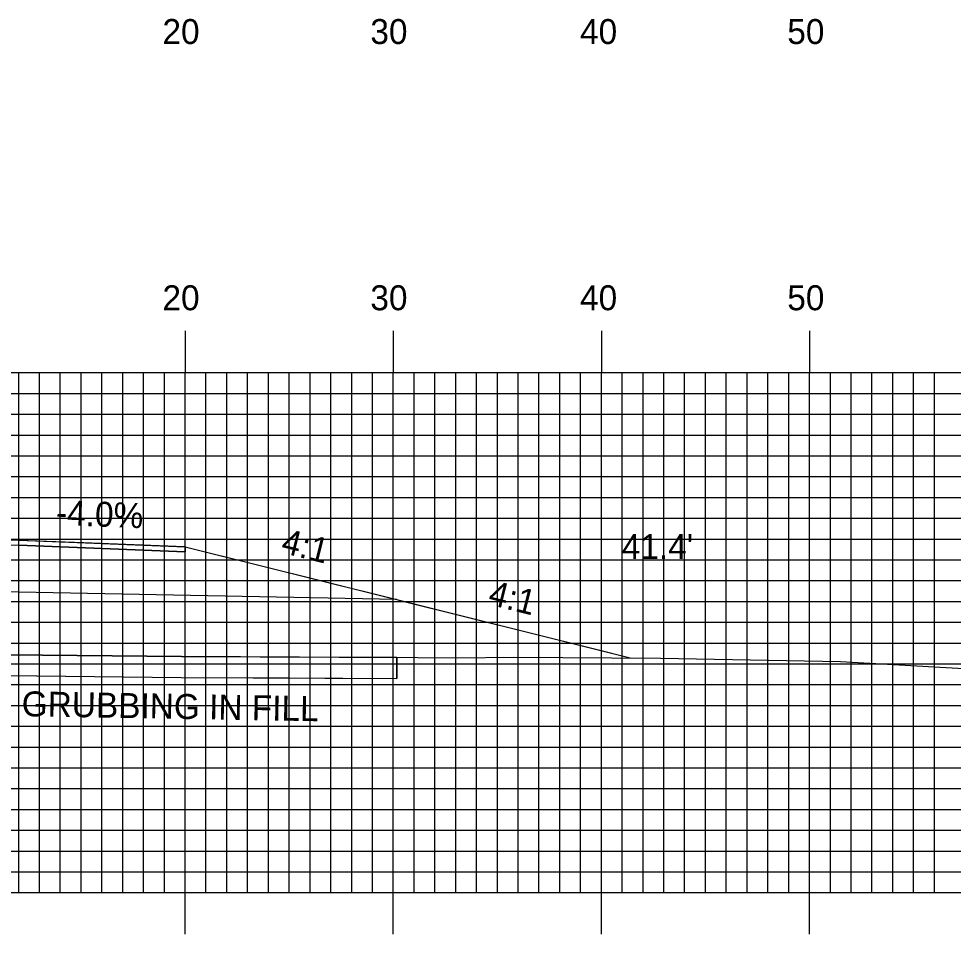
# Model space of a CAD drawing. Extents: x 1771629 to 1771972, y 442591 to 442811.
# Drawn here: x 1771806.58 to 1771851.49, y 442696.66 to 442740.68 of the extents above; entities that cross this region are included whole.
import ezdxf

# ---------------------------------------------------------------- set-up
doc = ezdxf.new("R2010")
doc.units = 0
for name, color, linetype in [('ANNOTATION', 7, 'Continuous'), ('D_Roadway_Centerline', 7, 'Continuous'), ('D_Roadway_Edge_Shoulder', 7, 'Continuous'), ('D_Roadway_SlopeLines', 7, 'Continuous'), ('D_Roadway_SubGrade', 7, 'Continuous'), ('D_Text_Standard', 7, 'Continuous'), ('GRUBBING IN FILL', 7, 'Continuous'), ('H_V ANNOTATION', 7, 'Continuous'), ('MAJOR', 7, 'Continuous'), ('MINOR', 7, 'Continuous'), ('S_Roadway_Centerline', 7, 'Continuous')]:
    doc.layers.add(name, color=color, linetype=linetype)

msp = doc.modelspace()

# ---------------------------------------------------------------- linework, layer by layer
at = {"layer": 'D_Roadway_Centerline'}
msp.add_lwpolyline([(1771760.497, 442711.776), (1771764.04, 442712.662), (1771764.407, 442712.753), (1771767.076, 442713.421), (1771774.552, 442715.29), (1771774.581, 442715.297), (1771776.908, 442715.39), (1771782.58, 442715.617), (1771794.576, 442715.857), (1771794.581, 442715.857), (1771806.579, 442715.617), (1771806.58, 442715.617), (1771809.705, 442715.492), (1771814.547, 442715.299), (1771814.58, 442715.297), (1771824.673, 442712.774), (1771824.754, 442712.753), (1771824.845, 442712.731), (1771834.313, 442710.363), (1771835.958, 442709.952)], dxfattribs=at)
at = {"layer": 'D_Roadway_Edge_Shoulder'}
msp.add_lwpolyline([(1771806.58, 442715.617), (1771814.58, 442715.297), (1771814.58, 442715.047), (1771806.58, 442715.367)], close=True, dxfattribs=at)
at = {"layer": 'D_Roadway_SlopeLines'}
msp.add_lwpolyline([(1771814.58, 442715.297), (1771824.754, 442712.753), (1771835.958, 442709.952)], dxfattribs=at)
at = {"layer": 'D_Roadway_SubGrade'}
msp.add_lwpolyline([(1771782.58, 442713.117), (1771764.406, 442712.753), (1771774.581, 442715.297), (1771774.581, 442715.047), (1771782.58, 442715.367), (1771794.581, 442715.607), (1771806.58, 442715.367), (1771814.58, 442715.047), (1771814.58, 442715.297), (1771824.754, 442712.753), (1771806.58, 442713.117), (1771794.581, 442713.357)], close=True, dxfattribs=at)
at = {"layer": 'GRUBBING IN FILL'}
msp.add_line((1771824.754, 442709.968), (1771824.754, 442708.968), dxfattribs=at)
msp.add_line((1771824.754, 442709.968), (1771824.754, 442708.968), dxfattribs=at)
msp.add_lwpolyline([(1771764.406, 442710.663), (1771769.384, 442710.401), (1771775.916, 442710.19), (1771784.299, 442709.937), (1771803.34, 442709.131), (1771806.049, 442709.097), (1771814.394, 442709.016), (1771824.754, 442708.968)], dxfattribs=at)
msp.add_lwpolyline([(1771764.406, 442710.663), (1771769.384, 442710.401), (1771775.916, 442710.19), (1771784.299, 442709.937), (1771803.34, 442709.131), (1771806.049, 442709.097), (1771814.394, 442709.016), (1771824.754, 442708.968)], dxfattribs=at)
msp.add_lwpolyline([(1771794.58, 442709.502), (1771803.34, 442709.131), (1771810.221, 442709.056), (1771814.394, 442709.016), (1771819.574, 442708.992), (1771824.754, 442708.968), (1771824.754, 442709.968), (1771820.08, 442709.99), (1771814.401, 442710.016), (1771806.06, 442710.097), (1771803.368, 442710.131), (1771794.58, 442710.503)], close=True, dxfattribs=at)
msp.add_lwpolyline([(1771794.58, 442709.502), (1771803.34, 442709.131), (1771810.221, 442709.056), (1771814.394, 442709.016), (1771819.574, 442708.992), (1771824.754, 442708.968), (1771824.754, 442709.968), (1771820.08, 442709.99), (1771814.401, 442710.016), (1771806.06, 442710.097), (1771803.368, 442710.131), (1771794.58, 442710.503)], close=True, dxfattribs=at)
at = {"layer": 'MAJOR'}
for p, q in [((1771814.58, 442725.669), (1771814.58, 442723.665)), ((1771824.58, 442725.669), (1771824.58, 442723.665)), ((1771834.58, 442725.669), (1771834.58, 442723.665)), ((1771844.58, 442725.669), (1771844.58, 442723.665)), ((1771654.58, 442723.665), (1771934.58, 442723.665)), ((1771654.58, 442723.665), (1771934.58, 442723.665)), ((1771814.58, 442698.665), (1771814.58, 442723.665)), ((1771824.58, 442698.665), (1771824.58, 442723.665)), ((1771834.58, 442698.665), (1771834.58, 442723.665)), ((1771844.58, 442698.665), (1771844.58, 442723.665)), ((1771654.58, 442718.665), (1771934.58, 442718.665)), ((1771654.58, 442713.665), (1771934.58, 442713.665)), ((1771654.58, 442708.665), (1771934.58, 442708.665)), ((1771654.58, 442703.665), (1771934.58, 442703.665)), ((1771654.58, 442698.665), (1771934.58, 442698.665)), ((1771654.58, 442698.665), (1771934.58, 442698.665)), ((1771814.58, 442696.661), (1771814.58, 442698.665)), ((1771824.58, 442696.661), (1771824.58, 442698.665)), ((1771834.58, 442696.661), (1771834.58, 442698.665)), ((1771844.58, 442696.661), (1771844.58, 442698.665))]:
    msp.add_line(p, q, dxfattribs=at)
at = {"layer": 'MINOR'}
for p, q in [((1771806.58, 442698.665), (1771806.58, 442723.665)), ((1771807.58, 442698.665), (1771807.58, 442723.665)), ((1771808.58, 442698.665), (1771808.58, 442723.665)), ((1771809.58, 442698.665), (1771809.58, 442723.665)), ((1771810.58, 442698.665), (1771810.58, 442723.665)), ((1771811.58, 442698.665), (1771811.58, 442723.665)), ((1771812.58, 442698.665), (1771812.58, 442723.665)), ((1771813.58, 442698.665), (1771813.58, 442723.665)), ((1771815.58, 442698.665), (1771815.58, 442723.665)), ((1771816.58, 442698.665), (1771816.58, 442723.665)), ((1771817.58, 442698.665), (1771817.58, 442723.665)), ((1771818.58, 442698.665), (1771818.58, 442723.665)), ((1771819.58, 442698.665), (1771819.58, 442723.665)), ((1771820.58, 442698.665), (1771820.58, 442723.665)), ((1771821.58, 442698.665), (1771821.58, 442723.665)), ((1771822.58, 442698.665), (1771822.58, 442723.665)), ((1771823.58, 442698.665), (1771823.58, 442723.665)), ((1771825.58, 442698.665), (1771825.58, 442723.665)), ((1771826.58, 442698.665), (1771826.58, 442723.665)), ((1771827.58, 442698.665), (1771827.58, 442723.665)), ((1771828.58, 442698.665), (1771828.58, 442723.665)), ((1771829.58, 442698.665), (1771829.58, 442723.665)), ((1771830.58, 442698.665), (1771830.58, 442723.665)), ((1771831.58, 442698.665), (1771831.58, 442723.665)), ((1771832.58, 442698.665), (1771832.58, 442723.665)), ((1771833.58, 442698.665), (1771833.58, 442723.665)), ((1771835.58, 442698.665), (1771835.58, 442723.665)), ((1771836.58, 442698.665), (1771836.58, 442723.665)), ((1771837.58, 442698.665), (1771837.58, 442723.665)), ((1771838.58, 442698.665), (1771838.58, 442723.665)), ((1771839.58, 442698.665), (1771839.58, 442723.665)), ((1771840.58, 442698.665), (1771840.58, 442723.665)), ((1771841.58, 442698.665), (1771841.58, 442723.665)), ((1771842.58, 442698.665), (1771842.58, 442723.665)), ((1771843.58, 442698.665), (1771843.58, 442723.665)), ((1771845.58, 442698.665), (1771845.58, 442723.665)), ((1771846.58, 442698.665), (1771846.58, 442723.665)), ((1771847.58, 442698.665), (1771847.58, 442723.665)), ((1771848.58, 442698.665), (1771848.58, 442723.665)), ((1771849.58, 442698.665), (1771849.58, 442723.665)), ((1771850.58, 442698.665), (1771850.58, 442723.665)), ((1771654.58, 442722.665), (1771934.58, 442722.665)), ((1771654.58, 442721.665), (1771934.58, 442721.665)), ((1771654.58, 442720.665), (1771934.58, 442720.665)), ((1771654.58, 442719.665), (1771934.58, 442719.665)), ((1771654.58, 442717.665), (1771934.58, 442717.665)), ((1771654.58, 442716.665), (1771934.58, 442716.665)), ((1771654.58, 442715.665), (1771934.58, 442715.665)), ((1771654.58, 442714.665), (1771934.58, 442714.665)), ((1771654.58, 442712.665), (1771934.58, 442712.665)), ((1771654.58, 442711.665), (1771934.58, 442711.665)), ((1771654.58, 442710.665), (1771934.58, 442710.665)), ((1771654.58, 442709.665), (1771934.58, 442709.665)), ((1771654.58, 442707.665), (1771934.58, 442707.665)), ((1771654.58, 442706.665), (1771934.58, 442706.665)), ((1771654.58, 442705.665), (1771934.58, 442705.665)), ((1771654.58, 442704.665), (1771934.58, 442704.665)), ((1771654.58, 442702.665), (1771934.58, 442702.665)), ((1771654.58, 442701.665), (1771934.58, 442701.665)), ((1771654.58, 442700.665), (1771934.58, 442700.665)), ((1771654.58, 442699.665), (1771934.58, 442699.665))]:
    msp.add_line(p, q, dxfattribs=at)
at = {"layer": 'S_Roadway_Centerline'}
msp.add_lwpolyline([(1771734.669, 442712.402), (1771743.955, 442712.204), (1771745.693, 442712.138), (1771748.383, 442712.136), (1771764.62, 442711.653), (1771769.426, 442711.401), (1771775.947, 442711.189), (1771784.335, 442710.937), (1771803.368, 442710.131), (1771806.06, 442710.097), (1771814.401, 442710.016), (1771825.759, 442709.964), (1771827.662, 442709.962), (1771830.368, 442709.98), (1771837.415, 442709.945), (1771846.068, 442709.775), (1771859.884, 442709)], dxfattribs=at)

# ---------------------------------------------------------------- texts
at = {"layer": 'ANNOTATION'}
for s, rotation, p in [('-4.0%', 357.7094, (1771808.355, 442716.348)), ('4:1', 345.9612, (1771819.133, 442715.021)), ('4:1', 345.9632, (1771829.085, 442712.532))]:
    msp.add_text(s, height=1.2, rotation=rotation, dxfattribs=at).set_placement(p)
at = {"layer": 'D_Text_Standard'}
msp.add_text("41.4'", height=1.2, dxfattribs=at).set_placement((1771835.559, 442714.701))
at = {"layer": 'GRUBBING IN FILL'}
msp.add_text('GRUBBING IN FILL', height=1.2, rotation=359.0192, dxfattribs=at).set_placement((1771806.718, 442707.149))
at = {"layer": 'H_V ANNOTATION'}
for s, p in [('20', (1771813.488, 442739.465)), ('30', (1771823.478, 442739.465)), ('40', (1771833.553, 442739.465)), ('50', (1771843.51, 442739.465)), ('20', (1771813.488, 442726.665)), ('30', (1771823.478, 442726.665)), ('40', (1771833.553, 442726.665)), ('50', (1771843.51, 442726.665))]:
    msp.add_text(s, height=1.2, dxfattribs=at).set_placement(p)

doc.saveas('drawing.dxf')
